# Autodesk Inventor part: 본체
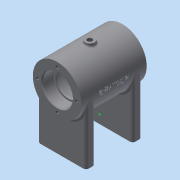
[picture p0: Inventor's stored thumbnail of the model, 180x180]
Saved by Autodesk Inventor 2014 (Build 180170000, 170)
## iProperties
Created: 2020-07
Part Number: 본체
Material: Generic
Document SubType Name: Modeling
Designer: kh
Density: 1 g/cm^3
Appearance: Default
Author: kh
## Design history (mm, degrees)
sketch "Sketch1"
  geometry: C1 r 26 at (64, 0); 1 further point
  constraints: 1 centre point
  dimensions: "d0" = 52 diameter of C1; "d1" = 64 distance of point (0, 0) C1.centre
extrude "Extrusion1" new body sketch "Sketch1" stored distance "d2" = 70; taper "d3" = 0 deg
sketch "Sketch2"
  geometry: L1 (-35, 90)-(-35, 38) reference; L2 (35, 38)-(35, 90) reference; L3 (-35, 64)-(35, 64); L4 (-35, 64)-(-35, 80); L5 (-35, 80)-(-23, 80); L6 (-23, 80)-(-23, 78); L7 (-23, 78)-(-21, 78); L8 (-21, 78)-(-21, 85); L9 (-21, 85)-(21, 85); L10 (21, 85)-(21, 78); L11 (21, 78)-(23, 78); L12 (23, 78)-(23, 80); L13 (23, 80)-(35, 80); 2 further points
  constraints: 22 end point, 4 parallel, 4 perpendicular, 3 collinear, 3 midpoint, 2 point on line
  dimensions: "d4" = 32 diameter of L5 L3; "d5" = 28 diameter of L7 L3; "d6" = 42 distance of L8.end L9.end; "d7" = 2 distance of L6.end L7.end; "d8" = 12 distance of L4.end L5.end; "d9" = 42 diameter of L9 L3; "d10" = 12 distance of L12.end L13.end
revolve "Revolution1" sketch "Sketch2" stored, may be unused: angle "d11" = 90 deg
workplane "Work Plane1"
sketch "Sketch3"
  geometry: L1 (64, 26)-(0, 26); L2 (0, 26)-(0, -26); L3 (0, -26)-(64, -26); L4 (64, -26)-(64, 26); A1 r 26 centre (64, 0) between (64, 26) and (64, -26) reference; 1 further point
  constraints: 8 end point, 2 point on circle, 2 tangent, 1 horizontal, 1 perpendicular
  dimensions: "d13" = 52 distance of L1.end L2.end
extrude "Extrusion2" join sketch "Sketch3" distance "d14" = 10; taper "d15" = 0 deg
workplane "Work Plane2"
sketch "Sketch4"
  geometry: L1 (64, -26)-(0, -26); L2 (0, -26)-(0, 26); L3 (0, 26)-(64, 26); A1 r 26 centre (64, 0) between (64, 26) and (64, -26) reference; 1 further point
  constraints: 6 end point, 1 horizontal, 1 parallel, 1 perpendicular, 1 point on circle, 1 tangent
extrude "Extrusion3" join sketch "Sketch4" distance "d17" = 10; taper "d18" = 0 deg
workplane "Work Plane3"
sketch "Sketch5"
  geometry: L1 (0, 0)-(0, -34); L2 (0, 0)-(-11.203, -30.781); L3 (-7.498, -20.6)-(-13.136, -18.548); L4 (-13.136, -18.548)-(-15.557, -25.199); L5 (-15.557, -25.199)-(-9.919, -27.251); L6 (-4.649, -30.316)-(-13.136, -18.548); L7 (-1.142, -23.54)-(-15.557, -25.199); A1 r 26 centre (0, 0) between (-26, 0) and (26, 0) reference; 2 further points
  constraints: 14 end point, 4 point on line, 1 midpoint, 1 parallel, 1 perpendicular, 1 point on circle, 1 vertical
  dimensions: "d20" = 20 deg angle of L1 L2; "d23" = 29 distance from line of L1.start L5
revolve "Revolution2" sketch "Sketch5" stored, may be unused: angle "d24" = 90 deg
sketch "Sketch6"
  geometry: L1 (0, 23)-(-5, 23); L2 (-5, 23)-(-5, 29); L3 (-5, 29)-(0, 29); L4 (5, 23)-(-5, 29); L5 (-5, 23)-(5, 29); L6 (0, 29)-(0, 23); 3 further points
  constraints: 12 end point, 2 midpoint, 1 horizontal, 1 parallel, 1 perpendicular, 1 vertical alignment, 1 other
  dimensions: "d25" = 10 distance of L2.end L5.end; "d26" = 3 distance from line of point (0, 26) L3
revolve "Revolution3" sketch "Sketch6" stored, may be unused: angle "d27" = 90 deg
sketch "Sketch7"
  geometry: 2 further points
hole "Hole1" sketch "Sketch7" at (0, 21) diameter "d29" = 3.242; stored, may be unused: countersink angle "d33" = 90 deg, drill point angle "d35" = 118 deg; dims "d30" = 8, "d31" = 4, "d32" = 2, "d34" = 10
pattern_circular "Circular Pattern1" dims angle "d37" = 360 deg
mirror "Mirror1"
workplane "Work Plane5"
sketch "Sketch9"
  geometry: L1 (-10, 0)-(-10, 52) reference; L2 (-10, 26)-(50, 26); L3 (0, 0)-(-10, 0) reference; 2 further points
  constraints: 2 end point, 1 midpoint, 1 perpendicular
  dimensions: "d41" = 5 distance from line of L1 point (-5, 46); "d42" = 26 distance between parallel lines of L3 L2; "d43" = 20 distance from line of L2 point (-5, 46)
hole "Hole2" sketch "Sketch9" at (-5, 46) diameter "d44" = 4.134; stored, may be unused: countersink angle "d48" = 90 deg, drill point angle "d50" = 118 deg; dims "d45" = 8, "d46" = 4, "d47" = 2, "d49" = 10
pattern_linear "Rectangular Pattern1" dims "d53" = 40
sketch "Sketch10"
  geometry: 2 further points
hole "Hole3" sketch "Sketch10" at (5, 46) diameter "d54" = 4.134; stored, may be unused: countersink angle "d58" = 90 deg, drill point angle "d60" = 118 deg; dims "d55" = 8, "d56" = 4, "d57" = 2, "d59" = 10
pattern_linear "Rectangular Pattern2" dims "d63" = 40
hole "Hole4" diameter "d66" = 5.188; stored, may be unused: countersink angle "d70" = 90 deg, drill point angle "d72" = 118 deg; dims "d64" = 10, "d65" = 10, "d67" = 8, "d68" = 4, "d69" = 2, "d71" = 18.25
sketch "Sketch11"
  geometry: C1 r 6 at (0, 0) reference; 1 further point
hole "Hole5" diameter "d75" = 5.188; stored, may be unused: countersink angle "d79" = 90 deg, drill point angle "d81" = 118 deg; dims "d73" = 10, "d74" = 10, "d76" = 8, "d77" = 4, "d78" = 2, "d80" = 18.25
workplane "Work Plane7"
sketch "Sketch12"
  geometry: L1 (-35, 26)-(-35, -26) reference; L2 (-35, 26)-(35, 26) reference; 2 further points
  constraints: 1 other
  dimensions: "d82" = 35 distance from line of L1 point (0, 0); "d83" = 26 distance from line of point (0, 0) L2
emboss "Emboss1" sketch "Sketch12" dims "d12" = 20, "d84" = 0.5, "d85" = 0
fillet "Fillet1" dims "d86" = 0.3
fillet "Fillet2" dims "d87" = 3
fillet "Fillet3" dims "d88" = 3
fillet "Fillet4" dims "d89" = 3
fillet "Fillet5" dims "d90" = 2
chamfer "Chamfer1" distance "d91" = 1; stored, may be unused: second distance "d92" = 2, angle "d93" = 45 deg
body "Solid1"
workplane "Work Plane4"
other parameters: "d19" = -35
